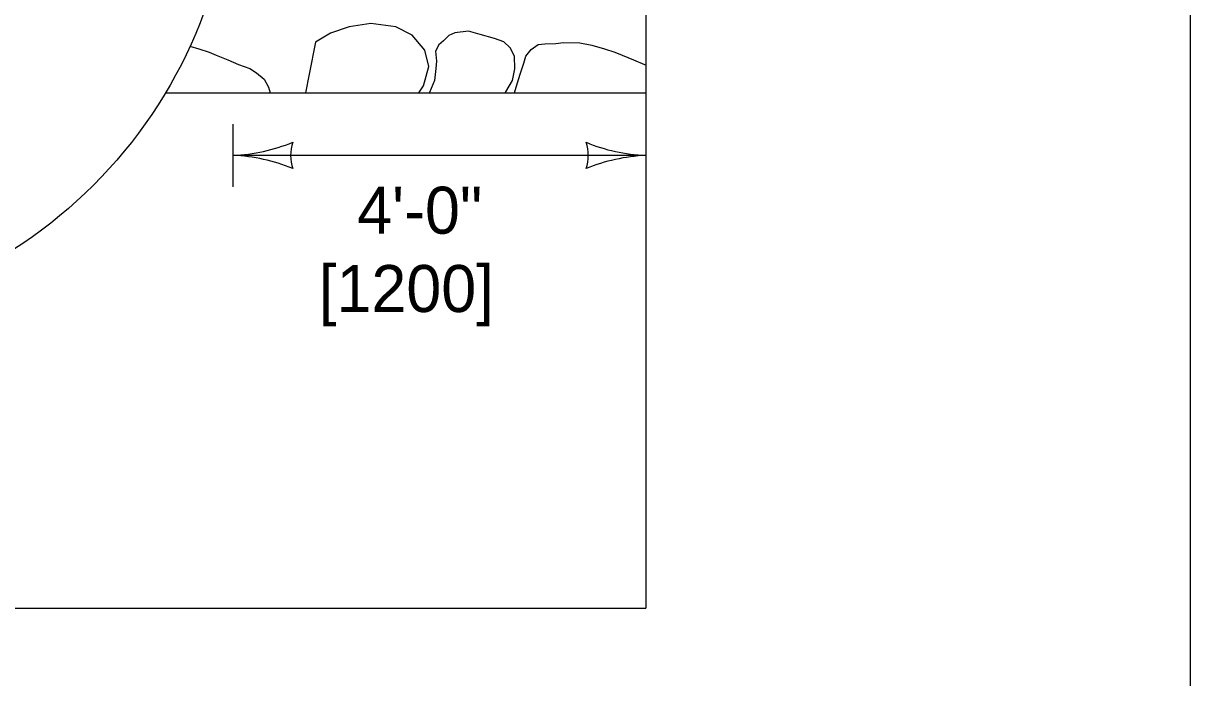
# Model space of a CAD drawing. Extents: x 49991.4 to 50021, y 49987.6 to 50011.4.
# Drawn here: x 50007.124 to 50008.615, y 50007.746 to 50008.582 of the extents above; entities that cross this region are included whole.
import ezdxf

# ---------------------------------------------------------------- set-up
doc = ezdxf.new("R2010")
doc.units = 0
for name, color, linetype in [('Default', 7, 'Continuous'), ('Level 1', 7, 'Continuous'), ('Level 2', 7, 'Continuous'), ('Level 3', 7, 'Continuous')]:
    doc.layers.add(name, color=color, linetype=linetype)

msp = doc.modelspace()

# ---------------------------------------------------------------- linework, layer by layer
at = {"layer": 'Default'}
for points in [[(50007.6289, 50008.4934), (50007.635, 50008.5023), (50007.6416, 50008.5269), (50007.6366, 50008.5478), (50007.6202, 50008.5672), (50007.5997, 50008.5776), (50007.5677, 50008.5821), (50007.5398, 50008.5776), (50007.516, 50008.5694), (50007.497, 50008.5579), (50007.4889, 50008.5172), (50007.4841, 50008.4934)], [(50007.7388, 50008.4934), (50007.7398, 50008.4948), (50007.7485, 50008.5093), (50007.7513, 50008.5239), (50007.7509, 50008.5403), (50007.7456, 50008.5508), (50007.7374, 50008.5586), (50007.7255, 50008.5627), (50007.7074, 50008.5679), (50007.6922, 50008.572), (50007.675, 50008.5702), (50007.6672, 50008.5664), (50007.6602, 50008.5597), (50007.6545, 50008.5545), (50007.65, 50008.5467), (50007.6516, 50008.5336), (50007.6508, 50008.5243), (50007.6491, 50008.509), (50007.6426, 50008.4937), (50007.6426, 50008.4934)], [(50007.3366, 50008.5528), (50007.3479, 50008.5497), (50007.3611, 50008.5452), (50007.3701, 50008.5415), (50007.3849, 50008.5355), (50007.3988, 50008.5296), (50007.4132, 50008.5243), (50007.4214, 50008.5187), (50007.4313, 50008.5109), (50007.437, 50008.5005), (50007.4389, 50008.4934)], [(50007.7509, 50008.4934), (50007.7534, 50008.5008), (50007.7583, 50008.5173), (50007.7632, 50008.5311), (50007.7657, 50008.54), (50007.7722, 50008.5486), (50007.7813, 50008.5549), (50007.7899, 50008.5561), (50007.8038, 50008.5564), (50007.8137, 50008.5576), (50007.8346, 50008.5572), (50007.8498, 50008.5542), (50007.8662, 50008.5497), (50007.8793, 50008.5452), (50007.8884, 50008.5415), (50007.9031, 50008.5355), (50007.9171, 50008.5296), (50007.9186, 50008.529)]]:
    msp.add_lwpolyline(points, dxfattribs=at)
at = {"layer": 'Level 1'}
for p, q in [((50007.9186, 50009.6783), (50007.9186, 50007.8352)), ((50007.3054, 50008.4934), (50007.9186, 50008.4934)), ((50005.6473, 50007.8352), (50007.9186, 50007.8352))]:
    msp.add_line(p, q, dxfattribs=at)
msp.add_lwpolyline([(50008.6146, 50011.2628), (50000.3356, 50011.2628), (50000.3356, 50000.0624), (50008.6146, 50000.0624)], close=True, dxfattribs=at)
msp.add_circle((50006.7828, 50008.8061), 0.609, dxfattribs=at)
at = {"layer": 'Level 3'}
for p, q in [((50007.3918, 50008.3734), (50007.3918, 50008.4534)), ((50007.9186, 50008.4134), (50007.3918, 50008.4134))]:
    msp.add_line(p, q, dxfattribs=at)
for centre, radius, start, end in [((50007.3803, 50008.6461), 0.233, 272.8273, 292.0772), ((50007.52, 50008.4134), 0.0548, 162.1388, 197.8612), ((50007.9278, 50008.6355), 0.2223, 247.456, 267.6395), ((50007.7904, 50008.4134), 0.0548, 342.1388, 17.8612), ((50007.3826, 50008.1913), 0.2223, 67.456, 87.6395), ((50007.9301, 50008.1807), 0.233, 92.8273, 112.0772)]:
    msp.add_arc(centre, radius, start, end, dxfattribs=at)

# ---------------------------------------------------------------- texts
at = {"layer": 'Level 2'}
for s, p in [('4\'-0"', (50007.5501, 50008.3134)), ('[1200]', (50007.5014, 50008.2134))]:
    msp.add_text(s, height=0.06, dxfattribs=at).set_placement(p)

doc.saveas('drawing.dxf')
